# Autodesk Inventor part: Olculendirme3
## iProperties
Shininess: 64.0
Length Units: 11269
Angle Units: 11279
Time Units: 11290
Mass Units: 11283
Length Display Precision: 3
Angle Display Precision: 2
Compacted: True
Part Number: Olculendirme3
Document SubType Name: Sheet Metal
Created: 2003-09
Material: Stainless Steel, 440C
Designer: Ronald Myers
Manufacturer: Standard
Standards Organization: Custom
Density: 1 g/cm^3
Flat Pattern Width: 9.1331 cm
Flat Pattern Length: 6.56655 cm
Flat Pattern Area: 59.9729 cm^2
Sheet Metal Rule: 1.0 mm Stainless
Density: 0.0
Volumn: 0.0
Area: 0.0
PropertySet Name: Model Information
Control State: 0
Master: False
Checked Out: False
Author: Ronald Myers
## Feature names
1. Hole1
2. Corner Round1
3. Corner Round2
4. Mirror3
5. Mirror4
6. Mirror5
7. Plate1
8. Plate2
9. Bend1
10. Plate3
11. Bend2
12. Plate4
13. Bend3
14. Plate5
15. Bend4
16. Plate6
17. Bend5
18. Plate7
19. Bend6
20. Cut1
21. Cut2
22. FlatPatternExtrusion2
